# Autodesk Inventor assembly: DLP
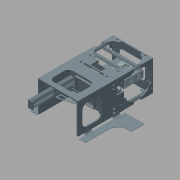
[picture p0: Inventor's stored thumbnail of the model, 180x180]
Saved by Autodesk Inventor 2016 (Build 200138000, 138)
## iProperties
Created: 2016-01
Part Number: DLP
Document SubType Name: Assembly
Designer: bongo_000
Title: DLP_stp.stp
Sending System: SIEMENS PLM Software NX 7.5
Preprocessor: ST-DEVELOPER v11
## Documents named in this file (21)
- C:\Users\bongo_000\Downloads\DLP\DLP.iam
- C:\Users\bongo_000\Downloads\DLP\VAT_ASSM.iam
- C:\Users\bongo_000\Downloads\DLP\91185A909_step.ipt
- C:\Users\bongo_000\Downloads\DLP\FRAME_ZMount.ipt
- C:\Users\bongo_000\Downloads\DLP\FRAME_SideWindow.ipt
- C:\Users\bongo_000\Downloads\DLP\VatHolder.ipt
- C:\Users\bongo_000\Downloads\DLP\FRAME_Rear.ipt
- C:\Users\bongo_000\Downloads\DLP\Frame_Mid.ipt
- C:\Users\bongo_000\Downloads\DLP\CornerBracket.ipt
- C:\Users\bongo_000\Downloads\DLP\CornerBracket_Projector.ipt
- C:\Users\bongo_000\Downloads\DLP\TSlot_300mm.ipt
- C:\Users\bongo_000\Downloads\DLP\FRAME_Base.ipt
- C:\Users\bongo_000\Downloads\DLP\projector_stp.ipt
- C:\Users\bongo_000\Downloads\DLP\TSlot_450mm.ipt
- C:\Users\bongo_000\Downloads\DLP\Projector_Plate.ipt
- C:\Users\bongo_000\Downloads\DLP\C-Beam Linear Actuator 500mm_step.iam
- C:\Users\bongo_000\Downloads\DLP\FrontBrace.ipt
- C:\Users\bongo_000\Downloads\DLP\Hinge_step.ipt
- C:\Users\bongo_000\Downloads\DLP\Door.ipt
- C:\Users\bongo_000\Downloads\DLP\FanVent_Projector.ipt
- C:\Users\bongo_000\Downloads\DLP\BED_ASSM.iam
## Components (37 placed, 37 different names)
1. VAT_ASSM_1070 [sub-assembly]
2. 91185A909_step_1071
3. 91185A909_step_1072
4. 91185A909_step_1073
5. 91185A909_step_1074
6. FRAME_ZMount_1075
7. FRAME_SideWindow_1076
8. VatHolder_1077
9. FRAME_Rear_1078
10. Frame_Mid_1079
11. CornerBracket_1080
12. CornerBracket_1081
13. CornerBracket_Projector_1082
14. CornerBracket_1083
15. TSlot_300mm_1084
16. TSlot_300mm_1085
17. TSlot_300mm_1086
18. TSlot_300mm_1087
19. CornerBracket_1088
20. CornerBracket_1089
21. CornerBracket_1090
22. CornerBracket_1091
23. FRAME_Base_1092
24. projector_stp_1093
25. TSlot_450mm_1094
26. TSlot_450mm_1095
27. Projector_Plate_1096
28. C-Beam Linear Actuator 500mm_step_1097 [sub-assembly]
29. FrontBrace_1098
30. Hinge_step_1099
31. Hinge_step_1100
32. Hinge_step_1101
33. Hinge_step_1102
34. Door_1103
35. Door_1104
36. FanVent_Projector_1105
37. BED_ASSM_1106 [sub-assembly]
